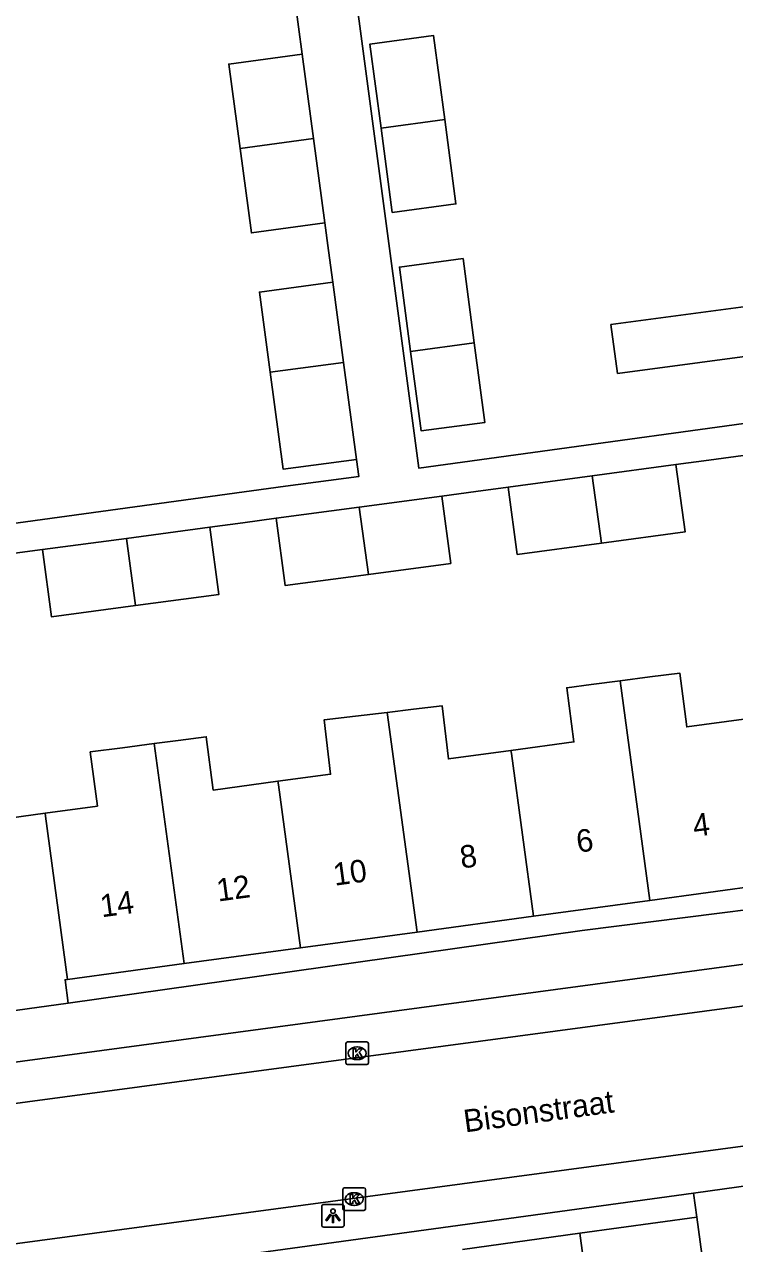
# Model space of a CAD drawing. Extents: x 163150 to 163546, y 380933 to 381635.
# Drawn here: x 163292.5 to 163323.9, y 381288.4 to 381342.3 of the extents above; entities that cross this region are included whole.
import ezdxf

# ---------------------------------------------------------------- set-up
doc = ezdxf.new("R2010")
doc.units = 0
for name, color, linetype in [('IMGEO_Kolk', 7, 'Continuous'), ('IMGEO_Lichtpunt', 7, 'Continuous'), ('IMGEO_Openbare_ruimte_label', 7, 'Continuous'), ('IMGEO_Pand', 7, 'Continuous'), ('IMGEO_Pand_nummerreeks', 7, 'Continuous'), ('IMGEO_Rijbaan_lokaal_open', 7, 'Continuous'), ('IMGEO_Voetpad_open', 7, 'Continuous')]:
    doc.layers.add(name, color=color, linetype=linetype)

msp = doc.modelspace()

# ---------------------------------------------------------------- linework, layer by layer
at = {"layer": 'IMGEO_Kolk'}
for p, q in [((163306.713, 381296.365), (163306.713, 381297.217)), ((163306.788, 381297.291), (163307.64, 381297.291)), ((163307.201, 381297.071), (163307.226, 381297.071)), ((163307.714, 381297.217), (163307.714, 381296.365)), ((163307.64, 381296.291), (163306.788, 381296.291)), ((163307.224, 381296.511), (163307.199, 381296.511)), ((163306.583, 381289.913), (163306.583, 381290.765)), ((163306.658, 381290.839), (163307.51, 381290.839)), ((163307.071, 381290.619), (163307.096, 381290.619)), ((163307.584, 381290.765), (163307.584, 381289.913)), ((163307.51, 381289.839), (163306.658, 381289.839)), ((163307.094, 381290.059), (163307.069, 381290.059))]:
    msp.add_line(p, q, dxfattribs=at)
for points in [[(163306.713, 381296.365), (163306.713, 381297.217)], [(163306.788, 381297.291), (163307.64, 381297.291)], [(163307.034, 381296.991), (163307.157, 381296.991), (163307.157, 381296.84), (163307.287, 381296.991), (163307.451, 381296.991), (163307.305, 381296.84), (163307.458, 381296.591), (163307.306, 381296.591), (163307.221, 381296.755), (163307.157, 381296.688), (163307.157, 381296.591), (163307.034, 381296.591), (163307.034, 381296.991)], [(163307.714, 381297.217), (163307.714, 381296.365)], [(163307.64, 381296.291), (163306.788, 381296.291)], [(163306.583, 381289.913), (163306.583, 381290.765)], [(163306.658, 381290.839), (163307.51, 381290.839)], [(163306.904, 381290.539), (163307.027, 381290.539), (163307.027, 381290.388), (163307.157, 381290.539), (163307.321, 381290.539), (163307.175, 381290.388), (163307.328, 381290.139), (163307.176, 381290.139), (163307.091, 381290.303), (163307.027, 381290.236), (163307.027, 381290.139), (163306.904, 381290.139), (163306.904, 381290.539)], [(163307.584, 381290.765), (163307.584, 381289.913)], [(163307.51, 381289.839), (163306.658, 381289.839)]]:
    msp.add_lwpolyline(points, dxfattribs=at)
for centre, start, end in [((163306.79, 381297.215), 91.552, 178.448), ((163306.79, 381297.215), 91.552, 178.448), ((163307.638, 381297.215), 1.552, 88.448), ((163307.638, 381297.215), 1.552, 88.448), ((163306.79, 381296.367), 181.552, 268.448), ((163306.79, 381296.367), 181.552, 268.448), ((163307.638, 381296.367), 271.552, 358.448), ((163307.638, 381296.367), 271.552, 358.448), ((163306.66, 381290.763), 91.552, 178.448), ((163306.66, 381290.763), 91.552, 178.448), ((163307.508, 381290.763), 1.552, 88.448), ((163307.508, 381290.763), 1.552, 88.448), ((163306.66, 381289.915), 181.552, 268.448), ((163306.66, 381289.915), 181.552, 268.448), ((163307.508, 381289.915), 271.552, 358.448), ((163307.508, 381289.915), 271.552, 358.448)]:
    msp.add_arc(centre, 0.0765, start, end, dxfattribs=at)
for centre, major_axis, ratio, start_param, end_param in [((163307.2, 381296.791), (-0.387, 0.002), 0.722429, 4.712389, 7.853982), ((163307.225, 381296.791), (-0.39, 0.002), 0.717154, 1.570796, 4.712389), ((163307.07, 381290.339), (-0.387, 0.002), 0.722429, 4.712389, 7.853982), ((163307.095, 381290.339), (-0.39, 0.002), 0.717154, 1.570796, 4.712389)]:
    msp.add_ellipse(centre, major_axis=major_axis, ratio=ratio, start_param=start_param, end_param=end_param, dxfattribs=at)
at = {"layer": 'IMGEO_Lichtpunt'}
for p, q in [((163305.645, 381290.002), (163305.645, 381289.195)), ((163305.645, 381290.002), (163305.645, 381289.195)), ((163306.547, 381290.097), (163305.739, 381290.097)), ((163306.547, 381290.097), (163305.739, 381290.097)), ((163306.641, 381289.195), (163306.641, 381290.002)), ((163306.641, 381289.195), (163306.641, 381290.002)), ((163305.739, 381289.101), (163306.547, 381289.101)), ((163305.739, 381289.101), (163306.547, 381289.101))]:
    msp.add_line(p, q, dxfattribs=at)
for points in [[(163306.019, 381289.666), (163306.058, 381289.638), (163305.87, 381289.376), (163305.832, 381289.403), (163306.019, 381289.666)], [(163306.121, 381289.618), (163306.168, 381289.618), (163306.168, 381289.296), (163306.121, 381289.296), (163306.121, 381289.618)], [(163306.231, 381289.638), (163306.269, 381289.665), (163306.456, 381289.403), (163306.417, 381289.375), (163306.231, 381289.638)]]:
    msp.add_lwpolyline(points, dxfattribs=at)
msp.add_circle((163306.144, 381289.8), 0.0994, dxfattribs=at)
for centre, start, end in [((163305.739, 381290.002), 90, 180), ((163305.739, 381290.002), 90, 180), ((163306.547, 381290.002), 0, 90), ((163306.547, 381290.002), 0, 90), ((163305.739, 381289.195), 180, 270), ((163305.739, 381289.195), 180, 270), ((163306.547, 381289.195), 270, 0), ((163306.547, 381289.195), 270, 360)]:
    msp.add_arc(centre, 0.0946, start, end, dxfattribs=at)
at = {"layer": 'IMGEO_Pand'}
for points in [[(163308.27, 381337.736), (163307.777, 381341.452), (163310.593, 381341.83), (163311.086, 381338.114)], [(163304.777, 381341.006), (163301.531, 381340.566), (163302.034, 381336.829)], [(163304.777, 381341.006), (163305.28, 381337.268)], [(163311.086, 381338.114), (163311.581, 381334.378), (163308.765, 381334), (163308.27, 381337.736)], [(163311.086, 381338.114), (163308.27, 381337.736)], [(163302.034, 381336.829), (163305.28, 381337.268)], [(163305.28, 381337.268), (163305.781, 381333.537)], [(163302.034, 381336.829), (163302.535, 381333.098), (163305.781, 381333.537)], [(163309.58, 381327.849), (163309.085, 381331.583), (163311.901, 381331.961), (163312.396, 381328.227)], [(163306.133, 381330.916), (163302.888, 381330.477), (163303.365, 381326.929)], [(163306.133, 381330.916), (163306.61, 381327.368)], [(163326.022, 381327.854), (163318.733, 381326.876), (163318.443, 381329.039), (163325.732, 381330.017)], [(163312.396, 381328.227), (163312.863, 381324.707), (163310.046, 381324.334), (163309.58, 381327.849)], [(163309.58, 381327.849), (163312.396, 381328.227)], [(163306.61, 381327.368), (163303.365, 381326.929)], [(163306.61, 381327.368), (163307.187, 381323.072)], [(163303.365, 381326.929), (163303.942, 381322.635), (163307.187, 381323.072)], [(163317.614, 381322.347), (163321.315, 381322.844)], [(163318.019, 381319.368), (163321.72, 381319.865), (163321.315, 381322.844)], [(163313.892, 381321.847), (163317.614, 381322.347)], [(163318.019, 381319.368), (163317.614, 381322.347)], [(163313.892, 381321.847), (163314.296, 381318.868), (163318.019, 381319.368)], [(163307.309, 381320.963), (163310.953, 381321.452)], [(163307.713, 381317.984), (163311.357, 381318.473), (163310.953, 381321.452)], [(163303.632, 381320.469), (163307.309, 381320.963)], [(163307.309, 381320.963), (163307.713, 381317.984)], [(163297.002, 381319.579), (163300.693, 381320.074)], [(163297.407, 381316.6), (163301.097, 381317.095), (163300.693, 381320.074)], [(163303.632, 381320.469), (163304.036, 381317.49), (163307.713, 381317.984)], [(163293.287, 381319.08), (163297.002, 381319.579)], [(163297.407, 381316.6), (163297.002, 381319.579)], [(163293.287, 381319.08), (163293.692, 381316.101), (163297.407, 381316.6)], [(163324.322, 381311.579), (163321.795, 381311.236), (163321.486, 381313.619), (163320.156, 381313.446), (163318.846, 381313.276)], [(163318.846, 381313.276), (163317.562, 381313.109), (163316.488, 381312.969), (163316.8, 381310.571), (163314.018, 381310.193)], [(163320.166, 381303.554), (163318.846, 381313.276)], [(163314.018, 381310.193), (163311.251, 381309.817), (163310.975, 381312.161), (163309.709, 381312.012), (163308.543, 381311.875)], [(163308.543, 381311.875), (163307.144, 381311.711), (163305.755, 381311.548), (163306.037, 381309.142), (163303.709, 381308.826)], [(163309.862, 381302.155), (163308.543, 381311.875)], [(163298.236, 381310.496), (163296.829, 381310.312), (163295.408, 381310.126), (163295.722, 381307.727), (163293.408, 381307.413)], [(163303.709, 381308.826), (163300.847, 381308.437), (163300.538, 381310.798), (163299.297, 381310.635), (163298.236, 381310.496)], [(163299.558, 381300.757), (163298.236, 381310.496)], [(163314.018, 381310.193), (163314.036, 381310.059), (163315.014, 381302.855)], [(163304.71, 381301.456), (163303.73, 381308.672), (163303.709, 381308.826)], [(163293.408, 381307.413), (163290.747, 381307.052), (163290.531, 381308.645), (163289.202, 381308.464), (163288.039, 381308.306)], [(163293.408, 381307.413), (163293.424, 381307.291), (163294.406, 381300.057)], [(163320.166, 381303.554), (163325.317, 381304.253)], [(163315.014, 381302.855), (163320.166, 381303.554)], [(163309.862, 381302.155), (163315.014, 381302.855)], [(163304.71, 381301.456), (163309.862, 381302.155)], [(163299.558, 381300.757), (163304.71, 381301.456)], [(163294.406, 381300.057), (163299.558, 381300.757)], [(163294.434, 381299.003), (163294.293, 381300.042), (163294.406, 381300.057)], [(163294.434, 381299.003), (163289.394, 381298.32), (163289.095, 381298.279)], [(163322.095, 381290.605), (163327.275, 381291.321), (163327.565, 381291.361)], [(163322.095, 381290.605), (163322.242, 381289.542)], [(163322.242, 381289.542), (163317.058, 381288.825)], [(163323.742, 381278.399), (163322.242, 381289.542)], [(163317.058, 381288.825), (163311.878, 381288.109)], [(163317.058, 381288.825), (163318.522, 381277.972)]]:
    msp.add_lwpolyline(points, dxfattribs=at)
at = {"layer": 'IMGEO_Rijbaan_lokaal_open'}
for points in [[(163330.836, 381299.757), (163284.351, 381293.529)], [(163329.119, 381293.327), (163285.136, 381287.427), (163285.037, 381287.407)]]:
    msp.add_lwpolyline(points, dxfattribs=at)
at = {"layer": 'IMGEO_Voetpad_open'}
for points in [[(163323.382, 381365.033), (163307.81, 381362.818), (163304.998, 381362.418), (163304.651, 381362.369), (163309.938, 381322.692), (163330.537, 381325.511)], [(163304.45, 381343.439), (163304.614, 381342.22), (163304.777, 381341.006)], [(163305.781, 381333.537), (163305.945, 381332.318), (163306.133, 381330.916)], [(163321.315, 381322.844), (163322.766, 381323.039), (163326.139, 381323.492)], [(163307.187, 381323.072), (163307.288, 381322.322), (163304.042, 381321.885), (163288.446, 381319.756)], [(163310.953, 381321.452), (163312.462, 381321.655), (163313.892, 381321.847)], [(163300.693, 381320.074), (163302.156, 381320.271), (163303.632, 381320.469)], [(163290.398, 381318.692), (163291.85, 381318.887), (163293.287, 381319.08)], [(163330.718, 381303.929), (163317.172, 381302.228), (163294.434, 381299.003)], [(163287.124, 381295.733), (163335.29, 381302.215)], [(163296.185, 381287.049), (163322.095, 381290.605)]]:
    msp.add_lwpolyline(points, dxfattribs=at)

# ---------------------------------------------------------------- texts
at = {"layer": 'IMGEO_Openbare_ruimte_label'}
msp.add_text('Bisonstraat', height=1, rotation=7.7007, dxfattribs=at).set_placement((163311.991, 381293.284))
at = {"layer": 'IMGEO_Pand_nummerreeks'}
for s, p in [('4', (163322.13, 381306.363)), ('6', (163316.978, 381305.664)), ('8', (163311.83, 381304.965)), ('10', (163306.22, 381304.203)), ('12', (163301.062, 381303.503)), ('14', (163295.914, 381302.805))]:
    msp.add_text(s, height=1, rotation=7.7292, dxfattribs=at).set_placement(p)

doc.saveas('drawing.dxf')
